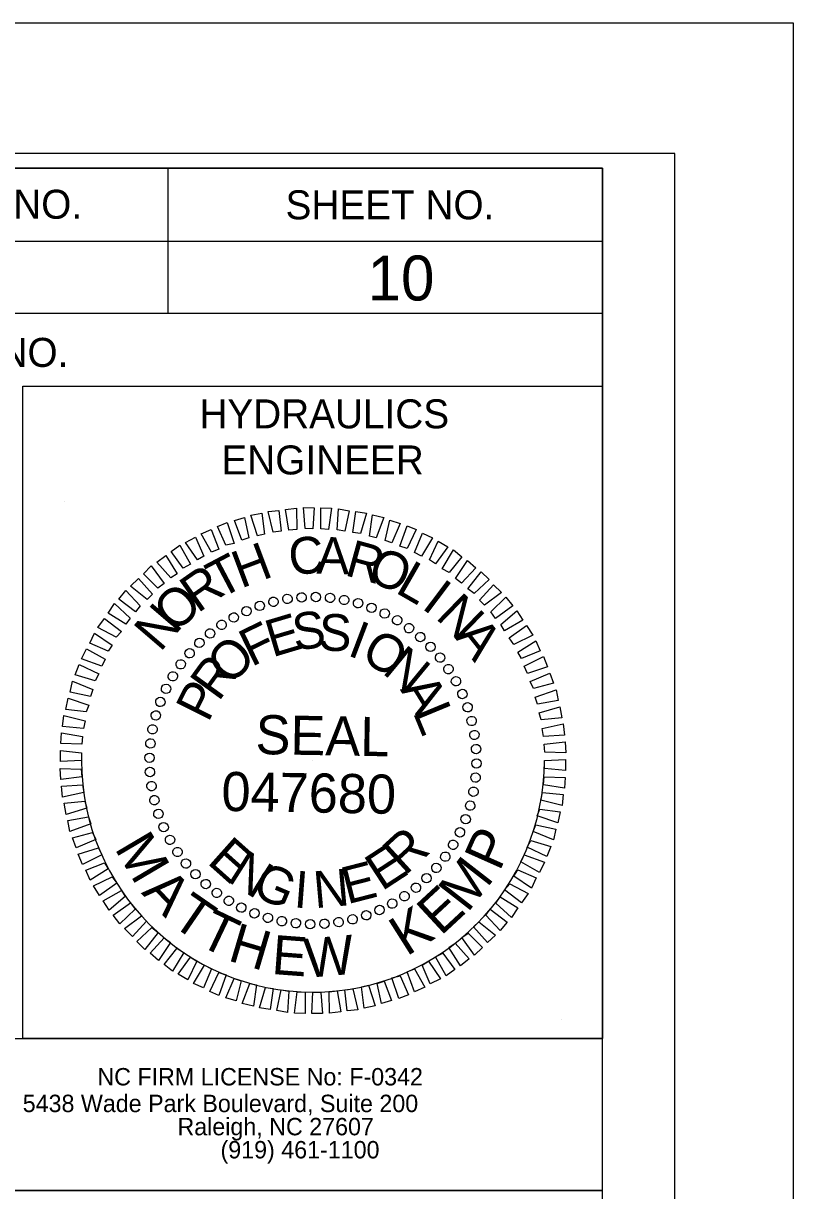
# Model space of a CAD drawing. Extents: x 2113763 to 2114783, y 714280 to 714940.
# Drawn here: x 2114702.8 to 2114782.6, y 714819.5 to 714940.3 of the extents above; entities that cross this region are included whole.
import ezdxf

# ---------------------------------------------------------------- set-up
doc = ezdxf.new("R2010")
doc.units = 0
for name, color, linetype in [('Old_Level_2', 7, 'Continuous'), ('Prop DSN Text', 7, 'Continuous'), ('Scratch_Level_0', 7, 'Continuous'), ('Sheet Block Title CELL', 7, 'Continuous'), ('Sheet Border Standard 30in CELL', 7, 'Continuous'), ('Sheet Cutting Line CELL', 7, 'Continuous'), ('Sheet Data Field CELL', 7, 'Continuous'), ('Sheet Plot Border Inside CELL', 7, 'Continuous'), ('Sheet Plot Border Outside CELL', 7, 'Continuous'), ('Sheet Profile CELL', 7, 'Continuous'), ('Sheet Sticker Exception Certification CELL', 7, 'Continuous')]:
    doc.layers.add(name, color=color, linetype=linetype)

msp = doc.modelspace()

# ---------------------------------------------------------------- linework, layer by layer
at = {"layer": 'Old_Level_2'}
for p, q in [((2114707.08, 714890.8), (2114707.08, 714890.8)), ((2114731.61, 714880.91), (2114731.61, 714880.91)), ((2114733.1, 714880.95), (2114733.1, 714880.95)), ((2114734.58, 714880.85), (2114734.58, 714880.85)), ((2114727.26, 714880.04), (2114727.26, 714880.04)), ((2114728.68, 714880.44), (2114728.68, 714880.44)), ((2114730.16, 714880.71), (2114730.16, 714880.71)), ((2114736.03, 714880.61), (2114736.03, 714880.61)), ((2114737.45, 714880.31), (2114737.45, 714880.31)), ((2114738.87, 714879.83), (2114738.87, 714879.83)), ((2114724.59, 714878.82), (2114724.59, 714878.82)), ((2114725.91, 714879.5), (2114725.91, 714879.5)), ((2114740.22, 714879.23), (2114740.22, 714879.23)), ((2114741.54, 714878.55), (2114741.54, 714878.55)), ((2114722.13, 714877.2), (2114722.13, 714877.2)), ((2114723.31, 714878.05), (2114723.31, 714878.05)), ((2114742.75, 714877.71), (2114742.75, 714877.71)), ((2114721.02, 714876.19), (2114721.02, 714876.19)), ((2114743.93, 714876.8), (2114743.93, 714876.8)), ((2114720, 714875.14), (2114720, 714875.14)), ((2114744.98, 714875.78), (2114744.98, 714875.78)), ((2114719.09, 714873.96), (2114719.09, 714873.96)), ((2114745.99, 714874.67), (2114745.99, 714874.67)), ((2114718.25, 714872.75), (2114718.25, 714872.75)), ((2114746.83, 714873.49), (2114746.83, 714873.49)), ((2114717.57, 714871.43), (2114717.57, 714871.43)), ((2114747.61, 714872.21), (2114747.61, 714872.21)), ((2114716.97, 714870.08), (2114716.97, 714870.08)), ((2114748.29, 714870.89), (2114748.29, 714870.89)), ((2114748.83, 714869.54), (2114748.83, 714869.54)), ((2114716.49, 714868.66), (2114716.49, 714868.66)), ((2114749.23, 714868.12), (2114749.23, 714868.12)), ((2114716.19, 714867.25), (2114716.19, 714867.25)), ((2114749.5, 714866.64), (2114749.5, 714866.64)), ((2114715.95, 714865.79), (2114715.95, 714865.79)), ((2114749.7, 714865.19), (2114749.7, 714865.19)), ((2114715.85, 714864.31), (2114715.85, 714864.31)), ((2114732.79, 714864.01), (2114732.79, 714864.01)), ((2114715.89, 714862.82), (2114715.89, 714862.82)), ((2114749.74, 714863.7), (2114749.74, 714863.7)), ((2114749.64, 714862.22), (2114749.64, 714862.22)), ((2114716.09, 714861.37), (2114716.09, 714861.37)), ((2114749.4, 714860.77), (2114749.4, 714860.77)), ((2114716.36, 714859.89), (2114716.36, 714859.89)), ((2114749.1, 714859.35), (2114749.1, 714859.35)), ((2114716.76, 714858.47), (2114716.76, 714858.47)), ((2114748.62, 714857.93), (2114748.62, 714857.93)), ((2114717.3, 714857.12), (2114717.3, 714857.12)), ((2114717.98, 714855.8), (2114717.98, 714855.8)), ((2114748.02, 714856.58), (2114748.02, 714856.58)), ((2114718.75, 714854.52), (2114718.75, 714854.52)), ((2114747.34, 714855.26), (2114747.34, 714855.26)), ((2114719.6, 714853.34), (2114719.6, 714853.34)), ((2114746.5, 714854.05), (2114746.5, 714854.05)), ((2114720.61, 714852.23), (2114720.61, 714852.23)), ((2114744.57, 714851.82), (2114744.57, 714851.82)), ((2114745.59, 714852.87), (2114745.59, 714852.87)), ((2114721.66, 714851.21), (2114721.66, 714851.21)), ((2114743.46, 714850.81), (2114743.46, 714850.81)), ((2114722.84, 714850.3), (2114722.84, 714850.3)), ((2114724.05, 714849.46), (2114724.05, 714849.46)), ((2114742.28, 714849.97), (2114742.28, 714849.97)), ((2114725.37, 714848.78), (2114725.37, 714848.78)), ((2114739.68, 714848.51), (2114739.68, 714848.51)), ((2114741, 714849.19), (2114741, 714849.19)), ((2114726.72, 714848.18), (2114726.72, 714848.18)), ((2114728.14, 714847.7), (2114728.14, 714847.7)), ((2114729.55, 714847.4), (2114729.55, 714847.4)), ((2114731.01, 714847.16), (2114731.01, 714847.16)), ((2114732.49, 714847.06), (2114732.49, 714847.06)), ((2114733.98, 714847.1), (2114733.98, 714847.1)), ((2114735.43, 714847.3), (2114735.43, 714847.3)), ((2114736.91, 714847.57), (2114736.91, 714847.57)), ((2114738.33, 714847.97), (2114738.33, 714847.97)), ((2114758.51, 714837.21), (2114758.51, 714837.21))]:
    msp.add_line(p, q, dxfattribs=at)
for points in [[(2114727.06, 714887.26), (2114726.35, 714889.39), (2114727.5, 714889.62), (2114727.77, 714887.43)], [(2114728.68, 714887.63), (2114728.14, 714889.79), (2114729.25, 714889.89), (2114729.49, 714887.73)], [(2114730.3, 714887.83), (2114729.93, 714889.99), (2114731.07, 714890.13), (2114731.11, 714887.93)], [(2114731.98, 714888), (2114731.82, 714890.2), (2114732.93, 714890.16), (2114732.79, 714887.97)], [(2114733.6, 714887.97), (2114733.6, 714890.16), (2114734.72, 714890.13), (2114734.41, 714887.93)], [(2114735.29, 714887.87), (2114735.43, 714890.06), (2114736.54, 714889.86), (2114736.1, 714887.73)], [(2114736.91, 714887.6), (2114737.22, 714889.76), (2114738.33, 714889.59), (2114737.72, 714887.5)], [(2114738.63, 714887.23), (2114738.97, 714889.42), (2114740.12, 714889.15), (2114739.34, 714887.06)], [(2114723.78, 714886.28), (2114722.91, 714888.24), (2114723.92, 714888.64), (2114724.63, 714886.48)], [(2114725.44, 714886.82), (2114724.66, 714888.85), (2114725.71, 714889.15), (2114726.15, 714887.06)], [(2114740.25, 714886.79), (2114740.76, 714888.88), (2114741.81, 714888.54), (2114740.96, 714886.55)], [(2114741.77, 714886.18), (2114742.55, 714888.31), (2114743.49, 714887.9), (2114742.55, 714885.94)], [(2114720.85, 714884.76), (2114719.6, 714886.58), (2114720.64, 714887.12), (2114721.49, 714885.17)], [(2114722.3, 714885.57), (2114721.22, 714887.46), (2114722.26, 714887.93), (2114723.04, 714885.88)], [(2114743.29, 714885.54), (2114744.13, 714887.53), (2114745.18, 714887.06), (2114744.03, 714885.17)], [(2114719.36, 714883.92), (2114718.11, 714885.64), (2114718.99, 714886.28), (2114720.1, 714884.32)], [(2114744.84, 714884.76), (2114745.75, 714886.69), (2114746.77, 714886.11), (2114745.48, 714884.36)], [(2114746.16, 714883.85), (2114747.34, 714885.81), (2114748.22, 714885.1), (2114746.9, 714883.45)], [(2114718.08, 714882.91), (2114716.63, 714884.53), (2114717.54, 714885.23), (2114718.72, 714883.34)], [(2114747.54, 714882.84), (2114748.79, 714884.69), (2114749.67, 714883.95), (2114748.18, 714882.37)], [(2114716.73, 714881.86), (2114715.24, 714883.34), (2114716.05, 714884.15), (2114717.37, 714882.33)], [(2114748.83, 714881.79), (2114750.21, 714883.55), (2114751.02, 714882.74), (2114749.47, 714881.29)], [(2114715.62, 714880.68), (2114713.89, 714882.06), (2114714.74, 714882.84), (2114716.16, 714881.22)], [(2114750.04, 714880.61), (2114751.49, 714882.2), (2114752.3, 714881.39), (2114750.55, 714880.07)], [(2114714.43, 714879.4), (2114712.68, 714880.71), (2114713.42, 714881.59), (2114714.91, 714880)], [(2114751.22, 714879.4), (2114752.77, 714880.91), (2114753.48, 714880), (2114751.69, 714878.72)], [(2114713.42, 714878.11), (2114711.6, 714879.26), (2114712.24, 714880.24), (2114713.86, 714878.75)], [(2114712.41, 714876.76), (2114710.52, 714877.78), (2114711.19, 714878.72), (2114712.95, 714877.37)], [(2114752.23, 714878.08), (2114753.89, 714879.5), (2114754.53, 714878.52), (2114752.64, 714877.44)], [(2114711.6, 714875.31), (2114709.68, 714876.16), (2114710.18, 714877.2), (2114712, 714875.95)], [(2114753.11, 714876.7), (2114754.9, 714877.98), (2114755.54, 714876.97), (2114753.58, 714876.02)], [(2114753.99, 714875.21), (2114755.88, 714876.39), (2114756.32, 714875.35), (2114754.39, 714874.57)], [(2114710.92, 714873.76), (2114708.83, 714874.54), (2114709.34, 714875.58), (2114711.26, 714874.5)], [(2114754.66, 714873.76), (2114756.66, 714874.77), (2114757.09, 714873.69), (2114755, 714873.02)], [(2114710.25, 714872.27), (2114708.16, 714872.88), (2114708.6, 714873.93), (2114710.62, 714872.98)], [(2114755.27, 714872.17), (2114757.33, 714873.05), (2114757.7, 714872), (2114755.61, 714871.46)], [(2114709.74, 714870.65), (2114707.65, 714871.09), (2114707.89, 714872.21), (2114710.01, 714871.36)], [(2114755.81, 714870.55), (2114757.97, 714871.33), (2114758.17, 714870.22), (2114756.05, 714869.84)], [(2114709.3, 714869.03), (2114707.21, 714869.3), (2114707.45, 714870.45), (2114709.57, 714869.74)], [(2114756.22, 714868.93), (2114758.34, 714869.57), (2114758.55, 714868.43), (2114756.42, 714868.22)], [(2114709.03, 714867.31), (2114706.87, 714867.52), (2114707.01, 714868.66), (2114709.2, 714868.12)], [(2114756.52, 714867.31), (2114758.71, 714867.79), (2114758.82, 714866.64), (2114756.66, 714866.5)], [(2114708.87, 714865.69), (2114706.67, 714865.76), (2114706.74, 714866.87), (2114708.93, 714866.5)], [(2114756.72, 714865.69), (2114758.92, 714865.96), (2114758.98, 714864.82), (2114756.79, 714864.88)], [(2114708.83, 714864.01), (2114706.64, 714863.9), (2114706.64, 714865.05), (2114708.83, 714864.82)], [(2114756.76, 714864.01), (2114758.95, 714864.11), (2114758.95, 714862.96), (2114756.76, 714863.2)], [(2114708.87, 714862.32), (2114706.67, 714862.05), (2114706.6, 714863.2), (2114708.8, 714863.13)], [(2114709.07, 714860.7), (2114706.87, 714860.23), (2114706.77, 714861.37), (2114708.93, 714861.51)], [(2114756.72, 714862.32), (2114758.92, 714862.25), (2114758.85, 714861.14), (2114756.66, 714861.51)], [(2114756.55, 714860.7), (2114758.71, 714860.5), (2114758.58, 714859.35), (2114756.39, 714859.89)], [(2114709.37, 714859.08), (2114707.25, 714858.44), (2114707.04, 714859.58), (2114709.17, 714859.79)], [(2114709.78, 714857.46), (2114707.62, 714856.68), (2114707.41, 714857.8), (2114709.54, 714858.17)], [(2114756.28, 714858.98), (2114758.38, 714858.71), (2114758.14, 714857.56), (2114756.01, 714858.27)], [(2114755.85, 714857.36), (2114757.94, 714856.92), (2114757.7, 714855.8), (2114755.58, 714856.65)], [(2114710.32, 714855.84), (2114708.26, 714854.96), (2114707.89, 714856.01), (2114709.98, 714856.55)], [(2114755.34, 714855.74), (2114757.43, 714855.13), (2114756.99, 714854.08), (2114754.97, 714855.03)], [(2114710.92, 714854.25), (2114708.93, 714853.24), (2114708.49, 714854.32), (2114710.59, 714854.99)], [(2114754.66, 714854.25), (2114756.76, 714853.48), (2114756.25, 714852.43), (2114754.33, 714853.51)], [(2114711.6, 714852.8), (2114709.71, 714851.62), (2114709.27, 714852.67), (2114711.19, 714853.44)], [(2114712.48, 714851.32), (2114710.69, 714850.03), (2114710.05, 714851.05), (2114712, 714851.99)], [(2114753.99, 714852.7), (2114755.91, 714851.86), (2114755.41, 714850.81), (2114753.58, 714852.06)], [(2114753.18, 714851.25), (2114755.07, 714850.24), (2114754.39, 714849.29), (2114752.64, 714850.64)], [(2114713.35, 714849.93), (2114711.7, 714848.51), (2114711.06, 714849.49), (2114712.95, 714850.57)], [(2114752.17, 714849.9), (2114753.99, 714848.75), (2114753.35, 714847.77), (2114751.73, 714849.26)], [(2114714.37, 714848.62), (2114712.81, 714847.1), (2114712.11, 714848.01), (2114713.89, 714849.29)], [(2114751.15, 714848.62), (2114752.91, 714847.3), (2114752.17, 714846.42), (2114750.68, 714848.01)], [(2114715.55, 714847.4), (2114714.1, 714845.81), (2114713.29, 714846.62), (2114715.04, 714847.94)], [(2114749.97, 714847.33), (2114751.69, 714845.95), (2114750.85, 714845.17), (2114749.43, 714846.79)], [(2114716.76, 714846.22), (2114715.38, 714844.46), (2114714.57, 714845.27), (2114716.12, 714846.73)], [(2114748.86, 714846.15), (2114750.34, 714844.67), (2114749.53, 714843.86), (2114748.22, 714845.68)], [(2114718.05, 714845.17), (2114716.8, 714843.32), (2114715.92, 714844.06), (2114717.4, 714845.65)], [(2114747.51, 714845.11), (2114748.96, 714843.49), (2114748.05, 714842.78), (2114746.87, 714844.67)], [(2114719.43, 714844.16), (2114718.25, 714842.2), (2114717.37, 714842.91), (2114718.69, 714844.57)], [(2114720.75, 714843.25), (2114719.83, 714841.33), (2114718.82, 714841.9), (2114720.1, 714843.65)], [(2114746.23, 714844.09), (2114747.48, 714842.37), (2114746.6, 714841.73), (2114745.48, 714843.69)], [(2114722.3, 714842.47), (2114721.45, 714840.48), (2114720.41, 714840.95), (2114721.56, 714842.84)], [(2114743.29, 714842.44), (2114744.37, 714840.55), (2114743.32, 714840.08), (2114742.55, 714842.14)], [(2114744.74, 714843.25), (2114745.99, 714841.43), (2114744.94, 714840.89), (2114744.1, 714842.84)], [(2114723.82, 714841.83), (2114723.04, 714839.71), (2114722.1, 714840.11), (2114723.04, 714842.07)], [(2114725.34, 714841.22), (2114724.83, 714839.13), (2114723.78, 714839.47), (2114724.63, 714841.46)], [(2114726.96, 714840.79), (2114726.62, 714838.59), (2114725.47, 714838.86), (2114726.25, 714840.95)], [(2114740.15, 714841.19), (2114740.93, 714839.17), (2114739.88, 714838.86), (2114739.44, 714840.95)], [(2114741.81, 714841.73), (2114742.68, 714839.77), (2114741.67, 714839.37), (2114740.96, 714841.53)], [(2114728.68, 714840.41), (2114728.37, 714838.25), (2114727.26, 714838.42), (2114727.87, 714840.52)], [(2114730.3, 714840.14), (2114730.16, 714837.95), (2114729.05, 714838.15), (2114729.49, 714840.28)], [(2114731.98, 714840.04), (2114731.98, 714837.85), (2114730.87, 714837.88), (2114731.17, 714840.08)], [(2114733.6, 714840.01), (2114733.77, 714837.82), (2114732.66, 714837.85), (2114732.79, 714840.04)], [(2114735.29, 714840.18), (2114735.66, 714838.02), (2114734.52, 714837.88), (2114734.48, 714840.08)], [(2114736.91, 714840.38), (2114737.45, 714838.22), (2114736.34, 714838.12), (2114736.1, 714840.28)], [(2114738.53, 714840.75), (2114739.24, 714838.63), (2114738.09, 714838.39), (2114737.82, 714840.58)]]:
    msp.add_lwpolyline(points, close=True, dxfattribs=at)
for centre, major_axis in [((2114728.7, 714880.43), (-0.118, 0.472)), ((2114730.15, 714880.73), (-0.076, 0.48)), ((2114731.61, 714880.89), (-0.034, 0.485)), ((2114733.09, 714880.93), (0.008, 0.486)), ((2114734.56, 714880.84), (0.051, 0.483)), ((2114736.02, 714880.62), (0.093, 0.477)), ((2114737.46, 714880.28), (0.134, 0.467)), ((2114725.91, 714879.47), (-0.198, 0.444)), ((2114727.28, 714880.01), (-0.158, 0.46)), ((2114738.86, 714879.81), (0.174, 0.454)), ((2114740.22, 714879.22), (0.213, 0.437)), ((2114723.33, 714878.04), (-0.272, 0.403)), ((2114724.59, 714878.81), (-0.236, 0.425)), ((2114741.51, 714878.52), (0.25, 0.417)), ((2114722.14, 714877.16), (-0.306, 0.378)), ((2114742.74, 714877.7), (0.286, 0.393)), ((2114743.9, 714876.78), (0.319, 0.367)), ((2114721.03, 714876.18), (-0.338, 0.35)), ((2114744.97, 714875.77), (0.35, 0.338)), ((2114720.02, 714875.11), (-0.367, 0.319)), ((2114745.95, 714874.66), (0.378, 0.306)), ((2114719.1, 714873.96), (-0.393, 0.286)), ((2114746.83, 714873.47), (0.403, 0.272)), ((2114718.28, 714872.72), (-0.417, 0.25)), ((2114747.6, 714872.21), (0.425, 0.236)), ((2114717.58, 714871.43), (-0.437, 0.213)), ((2114748.26, 714870.89), (0.444, 0.198)), ((2114716.99, 714870.07), (-0.454, 0.174)), ((2114748.8, 714869.52), (0.46, 0.158)), ((2114716.52, 714868.67), (-0.467, 0.134)), ((2114716.18, 714867.24), (-0.477, 0.093)), ((2114749.22, 714868.1), (0.472, 0.118)), ((2114749.51, 714866.65), (0.48, 0.076)), ((2114715.96, 714865.78), (-0.483, 0.051)), ((2114749.68, 714865.19), (0.485, 0.034)), ((2114715.87, 714864.3), (-0.486, 0.008)), ((2114749.72, 714863.71), (0.486, -0.008)), ((2114715.91, 714862.82), (-0.485, -0.034)), ((2114749.63, 714862.24), (0.483, -0.051)), ((2114716.07, 714861.36), (-0.48, -0.076)), ((2114716.37, 714859.91), (-0.472, -0.118)), ((2114749.41, 714860.78), (0.477, -0.093)), ((2114749.07, 714859.34), (0.467, -0.134)), ((2114716.79, 714858.49), (-0.46, -0.158)), ((2114748.6, 714857.94), (0.454, -0.174)), ((2114717.33, 714857.12), (-0.444, -0.198)), ((2114748.01, 714856.58), (0.437, -0.213)), ((2114717.99, 714855.8), (-0.425, -0.236)), ((2114747.31, 714855.29), (0.417, -0.25)), ((2114718.76, 714854.54), (-0.403, -0.272)), ((2114746.49, 714854.06), (0.393, -0.286)), ((2114719.64, 714853.35), (-0.378, -0.306)), ((2114745.57, 714852.9), (0.367, -0.319)), ((2114720.62, 714852.25), (-0.35, -0.338)), ((2114744.55, 714851.83), (0.338, -0.35)), ((2114721.69, 714851.23), (-0.319, -0.367)), ((2114722.84, 714850.31), (-0.286, -0.393)), ((2114743.45, 714850.85), (0.306, -0.378)), ((2114724.08, 714849.49), (-0.25, -0.417)), ((2114741, 714849.2), (0.236, -0.425)), ((2114742.26, 714849.97), (0.272, -0.403)), ((2114725.37, 714848.79), (-0.213, -0.437)), ((2114726.73, 714848.2), (-0.174, -0.454)), ((2114728.13, 714847.73), (-0.134, -0.467)), ((2114738.31, 714848), (0.158, -0.46)), ((2114739.68, 714848.54), (0.198, -0.444)), ((2114729.56, 714847.39), (-0.093, -0.477)), ((2114731.02, 714847.17), (-0.051, -0.483)), ((2114732.5, 714847.08), (-0.008, -0.486)), ((2114733.98, 714847.12), (0.034, -0.485)), ((2114735.44, 714847.29), (0.076, -0.48)), ((2114736.89, 714847.58), (0.118, -0.472))]:
    msp.add_ellipse(centre, major_axis=major_axis, ratio=0.999708, dxfattribs=at)
at = {"layer": 'Scratch_Level_0'}
msp.add_arc((2114732.79, 714864.01), 23.96, 180, 360, dxfattribs=at)
at = {"layer": 'Sheet Block Title CELL'}
msp.add_lwpolyline([(2114642.73, 714835.26), (2114762.73, 714835.26), (2114762.73, 714819.51), (2114642.73, 714819.51)], close=True, dxfattribs=at)
at = {"layer": 'Sheet Border Standard 30in CELL'}
msp.add_line((2114762.76, 714910.26), (2114762.76, 714902.76), dxfattribs=at)
msp.add_lwpolyline([(2114702.76, 714902.76), (2114762.76, 714902.76), (2114762.76, 714835.26), (2114702.76, 714835.26)], close=True, dxfattribs=at)
at = {"layer": 'Sheet Cutting Line CELL'}
for p, q in [((2114782.56, 714940.29), (2113762.56, 714940.29)), ((2114782.56, 714280.29), (2114782.56, 714940.29))]:
    msp.add_line(p, q, dxfattribs=at)
at = {"layer": 'Sheet Plot Border Inside CELL'}
msp.add_lwpolyline([(2113770.36, 714293.76), (2114770.26, 714293.76), (2114770.26, 714926.82), (2113770.36, 714926.82)], close=True, dxfattribs=at)
at = {"layer": 'Sheet Plot Border Outside CELL'}
msp.add_lwpolyline([(2113762.56, 714280.29), (2114782.56, 714280.29), (2114782.56, 714940.29), (2113762.56, 714940.29)], close=True, dxfattribs=at)
at = {"layer": 'Sheet Profile CELL'}
for p, q in [((2114717.76, 714925.26), (2114717.76, 714910.26)), ((2114642.73, 714917.76), (2114762.76, 714917.76))]:
    msp.add_line(p, q, dxfattribs=at)
for points in [[(2114762.76, 714925.29), (2113862.76, 714925.29), (2113862.76, 714295.29), (2114762.76, 714295.29)], [(2114642.73, 714925.29), (2114762.76, 714925.29), (2114762.76, 714910.26), (2114642.73, 714910.26)]]:
    msp.add_lwpolyline(points, close=True, dxfattribs=at)
at = {"layer": 'Sheet Sticker Exception Certification CELL'}
msp.add_line((2114642.73, 714819.51), (2114762.76, 714819.51), dxfattribs=at)

# ---------------------------------------------------------------- texts
at = {"layer": 'Old_Level_2'}
for s, height, rotation, p in [('C', 3.81, 6.2199, (2114730.47, 714883.14)), ('A', 3.81, 359.0203, (2114733.13, 714883.34)), ('H', 3.85, 20.6195, (2114725.34, 714881.79)), ('R', 3.83, 344.6211, (2114735.97, 714883.21)), ('O', 3.86, 337.4212, (2114738.23, 714882.7)), ('T', 3.88, 27.8198, (2114723.14, 714880.68)), ('L', 3.89, 330.2209, (2114741.2, 714881.45)), ('R', 3.91, 35.0205, (2114720.85, 714879.19)), ('I', 3.92, 323.0201, (2114743.93, 714879.83)), ('O', 3.93, 42.2217, (2114718.52, 714877.1)), ('N', 3.93, 315.8189, (2114745.38, 714878.79)), ('N', 3.93, 49.4235, (2114716.97, 714875.14)), ('F', 3.88, 25.967, (2114726.42, 714873.66)), ('E', 3.84, 16.6111, (2114728.58, 714874.67)), ('S', 3.81, 7.2556, (2114730.9, 714875.38)), ('S', 3.81, 357.9004, (2114733.33, 714875.41)), ('I', 3.86, 339.1896, (2114736.24, 714874.94)), ('O', 3.89, 329.8335, (2114737.59, 714874.47)), ('A', 3.93, 308.6172, (2114747.37, 714876.8)), ('O', 3.93, 44.6812, (2114724.19, 714871.67)), ('N', 3.92, 320.4766, (2114739.85, 714873.12)), ('R', 3.93, 54.0397, (2114723.01, 714870.01)), ('P', 3.9, 63.3989, (2114721.93, 714867.85)), ('A', 3.92, 301.7603, (2114741.77, 714871.36)), ('L', 3.88, 292.4009, (2114743.09, 714869.03)), ('SEAL', 4.049, 359, (2114726.82, 714864.68)), ('047680', 4.05, 359, (2114723.29, 714858.8)), ('M', 4.16, 300.5946, (2114712.19, 714854.95)), ('R', 3.93, 42.4814, (2114742.31, 714852.02)), ('P', 4.13, 65.9822, (2114752.11, 714852.45)), ('E', 3.93, 318.2769, (2114721.72, 714853.44)), ('N', 3.9, 327.634, (2114723.75, 714851.62)), ('E', 3.9, 33.1241, (2114739.92, 714850.44)), ('G', 3.86, 336.9902, (2114726.31, 714850.1)), ('E', 3.83, 14.4118, (2114736.34, 714849.12)), ('M', 4.18, 52.1673, (2114748.79, 714848.17)), ('A', 4.18, 314.4095, (2114714.95, 714850.29)), ('I', 3.81, 355.7012, (2114730.74, 714848.82)), ('N', 3.81, 5.0564, (2114733, 714848.72)), ('E', 4.18, 42.8526, (2114746.02, 714845.79)), ('T', 4.16, 325.4865, (2114717.92, 714847.12)), ('T', 4.12, 334.4865, (2114720.74, 714845)), ('K', 4.15, 32.342, (2114742.47, 714843.69)), ('H', 4.08, 343.4865, (2114723.86, 714843.35)), ('E', 4.05, 355.7279, (2114728.44, 714841.93)), ('W', 4.05, 5.0426, (2114732.08, 714841.51))]:
    msp.add_text(s, height=height, rotation=rotation, dxfattribs=at).set_placement(p)
at = {"layer": 'Prop DSN Text'}
for s, p in [('NC FIRM LICENSE No: F-0342', (2114710.47, 714830.39)), ('5438 Wade Park Boulevard, Suite 200', (2114702.74, 714827.63)), ('Raleigh, NC 27607', (2114718.76, 714825.23)), ('(919) 461-1100', (2114723.22, 714822.84))]:
    msp.add_text(s, height=1.8, rotation=0, dxfattribs=at).set_placement(p)
at = {"layer": 'Sheet Border Standard 30in CELL'}
for s, height, p in [('R/W SHEET NO.', 3.0001, (2114676.93, 714904.74)), ('HYDRAULICS', 3, (2114721.03, 714898.38)), ('ENGINEER', 3, (2114723.31, 714893.61))]:
    msp.add_text(s, height=height, rotation=0, dxfattribs=at).set_placement(p)
at = {"layer": 'Sheet Data Field CELL'}
msp.add_text('10', height=4.65, dxfattribs=at).set_placement((2114738.45, 714911.61))
at = {"layer": 'Sheet Profile CELL'}
for s, height, p in [('PROJECT REFERENCE NO.', 3.0001, (2114656.06, 714920.07)), ('SHEET NO.', 3, (2114729.95, 714920.01))]:
    msp.add_text(s, height=height, dxfattribs=at).set_placement(p)

doc.saveas('drawing.dxf')
